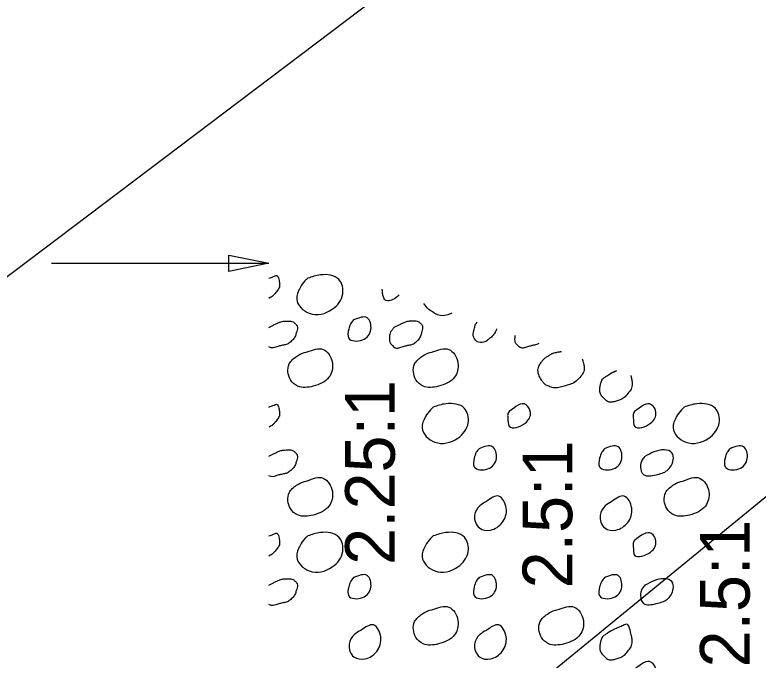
# Model space of a CAD drawing. Extents: x -1577 to 2037, y 0 to 220.
# Drawn here: x 153.58 to 174.53, y 157.06 to 175.24 of the extents above; entities that cross this region are included whole.
import ezdxf

# ---------------------------------------------------------------- set-up
doc = ezdxf.new("R2010")
doc.units = 0
for name, color, linetype in [('GE_P_Alignment_100_Stations', 7, 'Continuous'), ('PF_X_Ground_Line', 7, 'Continuous'), ('XS_P_Pavt_Surface', 7, 'Continuous')]:
    doc.layers.add(name, color=color, linetype=linetype)

msp = doc.modelspace()

# ---------------------------------------------------------------- linework, layer by layer
at = {"layer": 'GE_P_Alignment_100_Stations'}
for p, q in [((129.987, 150.211), (179.009, 187.242)), ((160.737, 150.211), (190.777, 174.777)), ((154.608, 168.239), (160.737, 168.239))]:
    msp.add_line(p, q, dxfattribs=at)
at = {"layer": 'PF_X_Ground_Line'}
msp.add_lwpolyline([(159.608, 168.466), (160.737, 168.239), (159.608, 168.011)], close=True, dxfattribs=at)
at = {"layer": 'XS_P_Pavt_Surface'}
for points, degree in [([(160.737, 167.815), (160.795, 167.839), (160.854, 167.862), (160.912, 167.884), (160.99, 167.914), (161.031, 167.74), (161.038, 167.666), (161.047, 167.566), (160.971, 167.462), (160.889, 167.363), (160.852, 167.319), (160.797, 167.279), (160.737, 167.25)], 3), ([(164.41, 167.347), (164.291, 167.222), (164.03, 167.137), (163.974, 167.279), (163.944, 167.355), (163.939, 167.434), (163.935, 167.513)], 3), ([(165.89, 166.832), (165.73, 166.758), (165.553, 166.747), (165.412, 166.831), (165.296, 166.899), (165.175, 166.994), (165.107, 167.104)], 3), ([(160.737, 166.432), (160.817, 166.472), (160.898, 166.513), (160.979, 166.553), (161.07, 166.598), (161.18, 166.607), (161.279, 166.61), (161.353, 166.612), (161.424, 166.595), (161.49, 166.529), (161.551, 166.469), (161.542, 166.389), (161.524, 166.326), (161.495, 166.221), (161.456, 166.114), (161.354, 166.029), (161.254, 165.946), (161.148, 165.934), (161.04, 165.909), (160.944, 165.887), (160.835, 165.835), (160.737, 165.882)], 3), ([(164.264, 166.428), (164.348, 166.47), (164.431, 166.511), (164.514, 166.553), (164.606, 166.598), (164.715, 166.607), (164.815, 166.61), (164.889, 166.612), (164.96, 166.595), (165.026, 166.529), (165.087, 166.469), (165.078, 166.389), (165.06, 166.326), (165.031, 166.221), (164.991, 166.114), (164.889, 166.029), (164.789, 165.946), (164.684, 165.934), (164.576, 165.909), (164.463, 165.883), (164.335, 165.816), (164.224, 165.915), (164.152, 165.98), (164.137, 166.057), (164.139, 166.131), (164.14, 166.197), (164.148, 166.276), (164.19, 166.331), (164.215, 166.364), (164.24, 166.396), (164.264, 166.428)], 3), ([(167.154, 166.391), (167.153, 166.384), (167.151, 166.378), (167.149, 166.372), (167.109, 166.264), (167.01, 166.156), (166.909, 166.078), (166.804, 165.997), (166.583, 166.011), (166.522, 166.134), (166.484, 166.212), (166.503, 166.302), (166.524, 166.38), (166.54, 166.435), (166.547, 166.498), (166.583, 166.544), (166.592, 166.556), (166.602, 166.568), (166.612, 166.58)], 3), ([(168.344, 165.976), (168.268, 165.939), (168.191, 165.928), (168.112, 165.909), (167.999, 165.883), (167.87, 165.816), (167.76, 165.915), (167.688, 165.98), (167.672, 166.057), (167.674, 166.131), (167.675, 166.156), (167.677, 166.182), (167.68, 166.208)], 3), ([(169.567, 165.55), (169.58, 165.508), (169.591, 165.468), (169.6, 165.434), (169.635, 165.305), (169.612, 165.148), (169.504, 165.028), (169.37, 164.88), (169.222, 164.824), (169.058, 164.775), (168.916, 164.734), (168.758, 164.718), (168.618, 164.778), (168.532, 164.814), (168.47, 164.876), (168.419, 164.956), (168.332, 165.09), (168.306, 165.275), (168.382, 165.401), (168.432, 165.485), (168.5, 165.559), (168.587, 165.614), (168.661, 165.661), (168.731, 165.705), (168.813, 165.723), (168.84, 165.729), (168.868, 165.734), (168.895, 165.74)], 3), ([(168.887, 165.739), (168.918, 165.744), (168.949, 165.749), (168.98, 165.755)], 2), ([(170.938, 165.072), (170.948, 165.034), (170.956, 164.997), (170.962, 164.969), (170.99, 164.838), (170.956, 164.691), (170.85, 164.564), (170.751, 164.444), (170.637, 164.387), (170.517, 164.351), (170.421, 164.322), (170.3, 164.317), (170.206, 164.41), (170.092, 164.523), (170.05, 164.655), (170.073, 164.769), (170.091, 164.86), (170.133, 164.98), (170.219, 165.037), (170.28, 165.078), (170.341, 165.116), (170.403, 165.156)], 3), ([(170.403, 165.156), (170.447, 165.175), (170.491, 165.194), (170.535, 165.213)], 2), ([(160.737, 164.184), (160.795, 164.208), (160.854, 164.231), (160.912, 164.254), (160.99, 164.283), (161.031, 164.11), (161.038, 164.035), (161.047, 163.936), (160.971, 163.832), (160.889, 163.733), (160.852, 163.688), (160.797, 163.648), (160.737, 163.619)], 3), ([(160.737, 162.802), (160.817, 162.842), (160.898, 162.882), (160.979, 162.922), (161.07, 162.968), (161.18, 162.977), (161.279, 162.98), (161.353, 162.982), (161.424, 162.965), (161.49, 162.899), (161.551, 162.839), (161.542, 162.759), (161.524, 162.696), (161.495, 162.591), (161.456, 162.484), (161.354, 162.399), (161.254, 162.316), (161.148, 162.304), (161.04, 162.279), (160.944, 162.256), (160.835, 162.204), (160.737, 162.252)], 3), ([(160.737, 160.554), (160.795, 160.578), (160.854, 160.601), (160.912, 160.623), (160.99, 160.653), (161.031, 160.479), (161.038, 160.405), (161.047, 160.305), (160.971, 160.201), (160.889, 160.102), (160.852, 160.058), (160.797, 160.018), (160.737, 159.989)], 3), ([(160.737, 159.171), (160.817, 159.211), (160.898, 159.252), (160.979, 159.292), (161.07, 159.337), (161.18, 159.346), (161.279, 159.349), (161.353, 159.351), (161.424, 159.334), (161.49, 159.268), (161.551, 159.208), (161.542, 159.128), (161.524, 159.065), (161.495, 158.96), (161.456, 158.853), (161.354, 158.768), (161.254, 158.685), (161.148, 158.673), (161.04, 158.648), (160.944, 158.626), (160.835, 158.574), (160.737, 158.621)], 3), ([(170.403, 157.895), (170.52, 157.945), (170.637, 157.996), (170.754, 158.046), (170.876, 158.098), (170.935, 157.831), (170.962, 157.708), (170.99, 157.577), (170.956, 157.43), (170.85, 157.303), (170.751, 157.183), (170.637, 157.126), (170.517, 157.09), (170.421, 157.061), (170.3, 157.056), (170.206, 157.149), (170.092, 157.262), (170.05, 157.394), (170.073, 157.508), (170.091, 157.599), (170.133, 157.719), (170.219, 157.776), (170.28, 157.817), (170.341, 157.855), (170.403, 157.895)], 3)]:
    msp.add_open_spline(points, degree=degree, dxfattribs=at)
for points in [[(161.836, 167.817), (162.192, 167.911), (162.713, 167.779), (162.82, 167.377), (162.524, 166.942), (161.876, 166.831), (161.522, 167.229), (161.617, 167.547), (161.755, 167.74), (161.836, 167.817)], [(163.127, 166.644), (163.509, 166.7), (163.613, 166.372), (163.373, 166.078), (162.986, 166.134), (162.989, 166.38), (163.047, 166.544), (163.127, 166.644)], [(161.815, 165.739), (162.269, 165.814), (162.529, 165.434), (162.432, 165.028), (161.986, 164.775), (161.546, 164.778), (161.347, 164.956), (161.31, 165.401), (161.515, 165.614), (161.741, 165.723), (161.824, 165.74)], [(165.351, 165.739), (165.805, 165.814), (166.064, 165.434), (165.968, 165.028), (165.522, 164.775), (165.082, 164.778), (164.883, 164.956), (164.846, 165.401), (165.051, 165.614), (165.277, 165.723), (165.359, 165.74)], [(165.372, 164.187), (165.728, 164.28), (166.249, 164.149), (166.356, 163.746), (166.06, 163.311), (165.412, 163.2), (165.058, 163.599), (165.153, 163.917), (165.291, 164.109), (165.372, 164.187)], [(167.509, 164.061), (167.984, 164.254), (168.109, 164.035), (167.96, 163.733), (167.51, 163.649), (167.471, 163.889), (167.475, 164.009), (167.509, 164.061)], [(171.044, 164.061), (171.519, 164.254), (171.645, 164.035), (171.496, 163.733), (171.046, 163.649), (171.007, 163.889), (171.011, 164.009), (171.044, 164.061)], [(172.444, 164.187), (172.799, 164.28), (173.32, 164.149), (173.428, 163.746), (173.132, 163.311), (172.484, 163.2), (172.129, 163.599), (172.224, 163.917), (172.363, 164.109), (172.444, 164.187)], [(166.663, 163.014), (167.044, 163.07), (167.149, 162.741), (166.909, 162.447), (166.522, 162.504), (166.524, 162.75), (166.583, 162.913), (166.663, 163.014)], [(170.199, 163.014), (170.58, 163.07), (170.684, 162.741), (170.444, 162.447), (170.058, 162.504), (170.06, 162.75), (170.119, 162.913), (170.199, 163.014)], [(171.336, 162.797), (171.586, 162.922), (171.887, 162.98), (172.098, 162.899), (172.132, 162.696), (171.961, 162.399), (171.648, 162.279), (171.296, 162.285), (171.21, 162.501), (171.262, 162.701), (171.336, 162.797)], [(173.734, 163.014), (174.116, 163.07), (174.22, 162.741), (173.98, 162.447), (173.594, 162.504), (173.596, 162.75), (173.654, 162.913), (173.734, 163.014)], [(161.815, 162.108), (162.269, 162.184), (162.529, 161.804), (162.432, 161.397), (161.986, 161.145), (161.546, 161.147), (161.347, 161.326), (161.31, 161.771), (161.515, 161.984), (161.741, 162.092), (161.824, 162.11)], [(172.423, 162.108), (172.877, 162.184), (173.136, 161.804), (173.039, 161.397), (172.594, 161.145), (172.154, 161.147), (171.954, 161.326), (171.918, 161.771), (172.123, 161.984), (172.349, 162.092), (172.431, 162.11)], [(166.867, 161.526), (167.219, 161.676), (167.426, 161.338), (167.314, 160.933), (166.981, 160.721), (166.67, 160.78), (166.537, 161.139), (166.683, 161.406), (166.867, 161.526)], [(170.403, 161.526), (170.754, 161.676), (170.962, 161.338), (170.85, 160.933), (170.517, 160.721), (170.206, 160.78), (170.073, 161.139), (170.219, 161.406), (170.403, 161.526)], [(161.836, 160.556), (162.192, 160.65), (162.713, 160.518), (162.82, 160.116), (162.524, 159.681), (161.876, 159.57), (161.522, 159.968), (161.617, 160.286), (161.755, 160.479), (161.836, 160.556)], [(165.372, 160.556), (165.728, 160.65), (166.249, 160.518), (166.356, 160.116), (166.06, 159.681), (165.412, 159.57), (165.058, 159.968), (165.153, 160.286), (165.291, 160.479), (165.372, 160.556)], [(171.044, 160.431), (171.519, 160.623), (171.645, 160.405), (171.496, 160.102), (171.046, 160.018), (171.007, 160.258), (171.011, 160.379), (171.044, 160.431)], [(163.127, 159.383), (163.509, 159.439), (163.613, 159.111), (163.373, 158.817), (162.986, 158.873), (162.989, 159.119), (163.047, 159.283), (163.127, 159.383)], [(166.663, 159.383), (167.044, 159.439), (167.149, 159.111), (166.909, 158.817), (166.522, 158.873), (166.524, 159.119), (166.583, 159.283), (166.663, 159.383)], [(170.199, 159.383), (170.58, 159.439), (170.684, 159.111), (170.444, 158.817), (170.058, 158.873), (170.06, 159.119), (170.119, 159.283), (170.199, 159.383)], [(171.336, 159.167), (171.586, 159.292), (171.887, 159.349), (172.098, 159.268), (172.132, 159.065), (171.961, 158.768), (171.648, 158.648), (171.296, 158.654), (171.21, 158.87), (171.262, 159.07), (171.336, 159.167)], [(165.351, 158.478), (165.805, 158.553), (166.064, 158.173), (165.968, 157.767), (165.522, 157.514), (165.082, 157.517), (164.883, 157.695), (164.846, 158.14), (165.051, 158.353), (165.277, 158.462), (165.359, 158.479)], [(168.887, 158.478), (169.341, 158.553), (169.6, 158.173), (169.504, 157.767), (169.058, 157.514), (168.618, 157.517), (168.419, 157.695), (168.382, 158.14), (168.587, 158.353), (168.813, 158.462), (168.895, 158.479)], [(163.331, 157.895), (163.683, 158.046), (163.89, 157.708), (163.779, 157.303), (163.445, 157.09), (163.134, 157.149), (163.001, 157.508), (163.147, 157.776), (163.331, 157.895)], [(166.867, 157.895), (167.219, 158.046), (167.426, 157.708), (167.314, 157.303), (166.981, 157.09), (166.67, 157.149), (166.537, 157.508), (166.683, 157.776), (166.867, 157.895)], [(171.044, 156.8), (171.519, 156.993), (171.645, 156.774), (171.496, 156.472), (171.046, 156.388), (171.007, 156.628), (171.011, 156.748), (171.044, 156.8)]]:
    msp.add_spline(points, degree=3, dxfattribs=at)

# ---------------------------------------------------------------- texts
at = {"layer": 'GE_P_Alignment_100_Stations'}
for s, p in [('2.25:1', (164.287, 159.741)), ('2.5:1', (169.287, 159.08)), ('2.5:1', (174.287, 156.85))]:
    msp.add_text(s, height=1.4, rotation=90, dxfattribs=at).set_placement(p)

doc.saveas('drawing.dxf')
